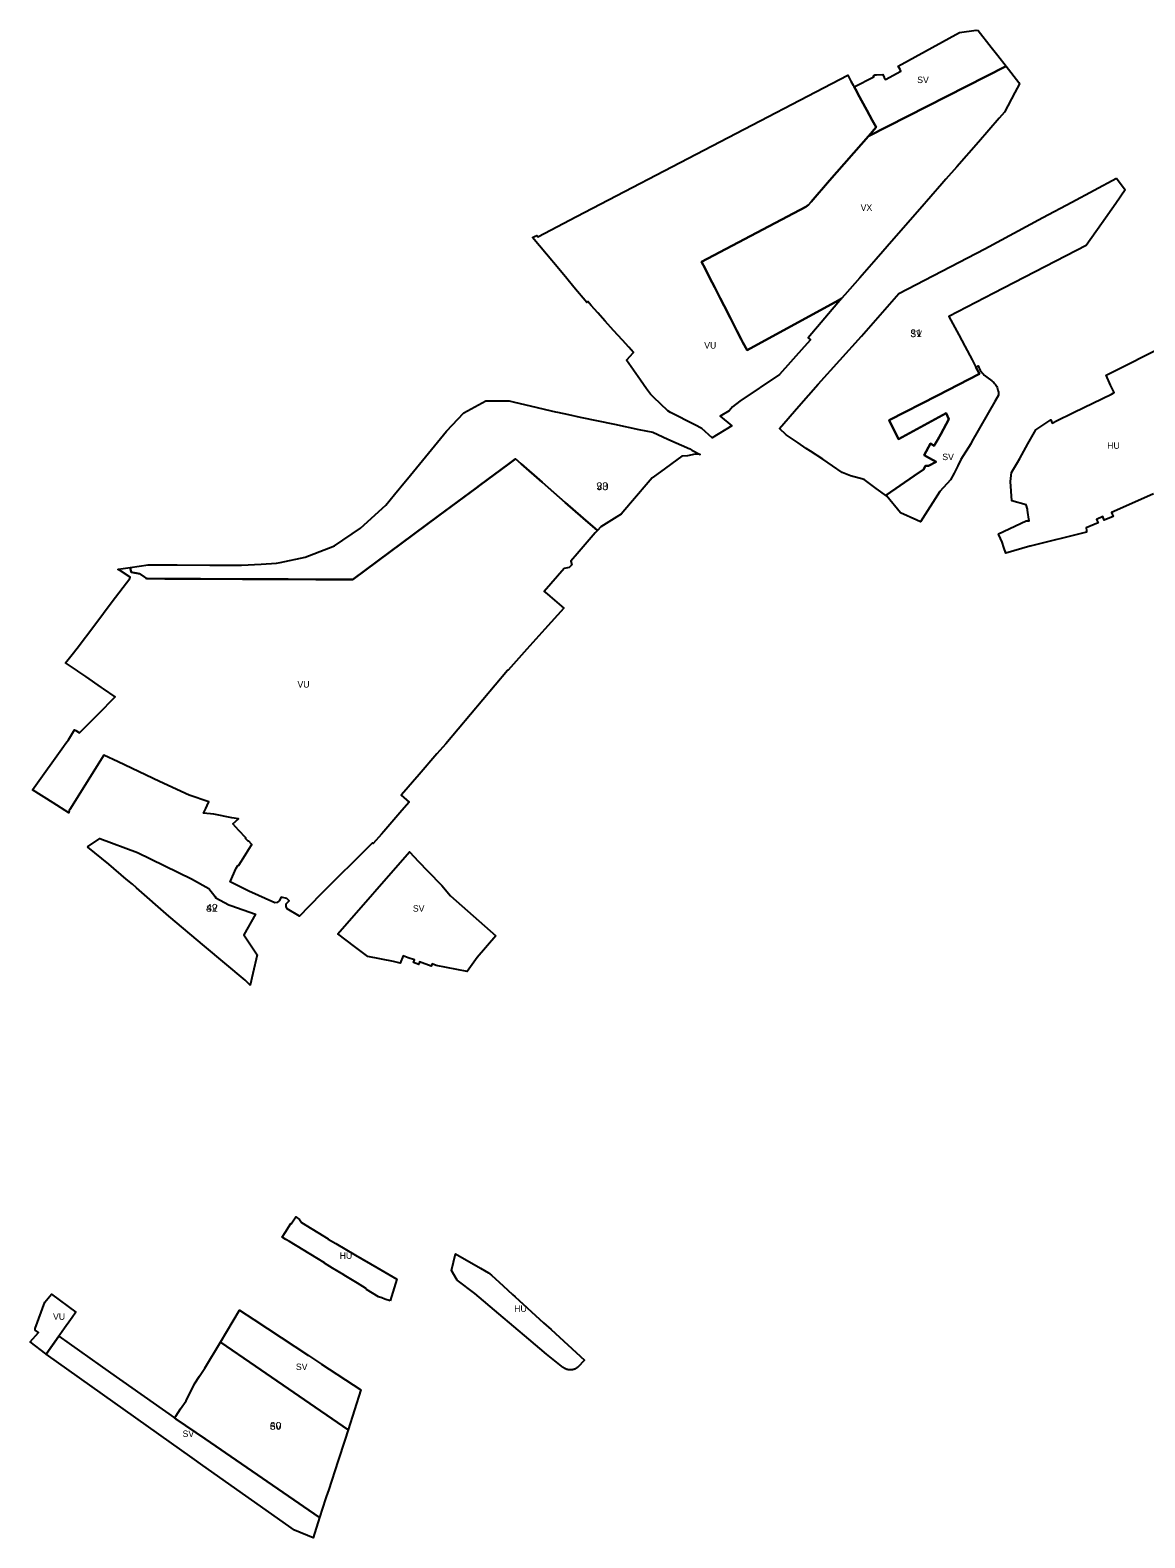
# Model space of a CAD drawing. Extents: x -537011 to -534997, y -1176103 to -1174159.
# Drawn here: x -536797 to -535938, y -1176103 to -1174942 of the extents above; entities that cross this region are included whole.
import ezdxf

# ---------------------------------------------------------------- set-up
doc = ezdxf.new("R2010")
doc.units = 0
for name, color, linetype in [('90510013', 7, 'Continuous'), ('90510023', 7, 'Continuous'), ('90530013', 7, 'Continuous'), ('90570013', 7, 'Continuous'), ('90570023', 7, 'Continuous'), ('90610013', 7, 'Continuous'), ('ID_navrh', 7, 'Continuous')]:
    doc.layers.add(name, color=color, linetype=linetype)

msp = doc.modelspace()

# ---------------------------------------------------------------- linework, layer by layer
at = {"layer": '90510013'}
for points in [[(-536045.18, -1174970.17), (-536045.73, -1174970.45), (-536151.28, -1175023.87), (-536145.37, -1175017.08), (-536148.37, -1175011.57), (-536152.47, -1175004.02), (-536159.31, -1174991.43), (-536160.25, -1174989.71), (-536162.24, -1174986.05), (-536147, -1174978.2), (-536147.32, -1174977.4), (-536146.01, -1174976.8), (-536145.01, -1174976.76), (-536140.21, -1174976.54), (-536138.99, -1174978.78), (-536138.15, -1174980.33), (-536126.13, -1174973.87), (-536126.86, -1174972.63), (-536128.29, -1174970.2), (-536081.08, -1174944.24), (-536068.21, -1174942.34), (-536066.78, -1174942.48), (-536056.76, -1174955.33), (-536051.59, -1174961.96)], [(-536136.94, -1175301.28), (-536137.54, -1175300.54), (-536115.98, -1175285.62), (-536108.91, -1175280.72), (-536107.34, -1175278), (-536104.81, -1175277.91), (-536098.94, -1175274.82), (-536104.15, -1175271.89), (-536108.34, -1175269.54), (-536103.41, -1175260.78), (-536100.55, -1175262.46), (-536100.03, -1175261.54), (-536097.74, -1175257.55), (-536095.46, -1175253.58), (-536089.15, -1175241.96), (-536091.37, -1175237.36), (-536128.04, -1175257.3), (-536135.13, -1175242.6), (-536098, -1175223.64), (-536065.59, -1175207.09), (-536068.42, -1175201.8), (-536066.77, -1175200.96), (-536066.26, -1175202.08), (-536065.69, -1175203.16), (-536065.05, -1175204.21), (-536064.36, -1175205.22), (-536063.6, -1175206.19), (-536062.79, -1175207.11), (-536061.93, -1175207.99), (-536061.02, -1175208.81), (-536060.06, -1175209.57), (-536056.07, -1175212.52), (-536055.33, -1175213.1), (-536054.64, -1175213.73), (-536053.99, -1175214.42), (-536053.41, -1175215.15), (-536052.88, -1175215.93), (-536052.42, -1175216.75), (-536052.02, -1175217.6), (-536051.69, -1175218.48), (-536051.43, -1175219.38), (-536051.24, -1175220.3), (-536051.12, -1175221.23), (-536051.08, -1175222.17), (-536051.13, -1175223.39), (-536053.84, -1175228.22), (-536058.69, -1175236.86), (-536066.56, -1175250.59), (-536071.45, -1175259.11), (-536072.44, -1175260.84), (-536079.94, -1175273.05), (-536082.34, -1175277.81), (-536085.27, -1175283.61), (-536088.03, -1175288.6), (-536096.32, -1175297.69), (-536111.06, -1175320.99), (-536113.86, -1175319.75), (-536126.39, -1175314.2)], [(-536438.2, -1175639.85), (-536452.58, -1175656.54), (-536460.22, -1175667.35), (-536468.28, -1175665.81), (-536484.22, -1175662.75), (-536484.19, -1175662.58), (-536487.36, -1175661.38), (-536488.15, -1175663.14), (-536496.94, -1175659.94), (-536497.69, -1175661.96), (-536501.75, -1175660.46), (-536501.02, -1175658.45), (-536505.74, -1175656.72), (-536509.74, -1175655.18), (-536511.84, -1175660.79), (-536517.13, -1175659.73), (-536536.94, -1175655.74), (-536547.03, -1175648.06), (-536553.54, -1175643.15), (-536560.04, -1175638.23), (-536504.76, -1175575.16), (-536497.76, -1175582.55), (-536490.76, -1175589.93), (-536479.81, -1175600.97), (-536473.11, -1175608.92)], [(-536552.03, -1176020.35), (-536623.36, -1175971.27), (-536650.39, -1175952.67), (-536635.62, -1175928.21), (-536624.7, -1175935.39), (-536582.47, -1175963.15), (-536572.61, -1175969.63), (-536542.24, -1175989.59)], [(-536774.84, -1175948.16), (-536735.05, -1175976.3), (-536685.79, -1176011.14), (-536684.52, -1176012.04), (-536662.25, -1176027.33), (-536574.14, -1176087.83), (-536579.09, -1176103.49), (-536593.43, -1176097.56), (-536663.87, -1176047.79), (-536672.22, -1176041.85), (-536784.64, -1175961.96)]]:
    msp.add_lwpolyline(points, close=True, dxfattribs=at)
at = {"layer": '90510023'}
for points in [[(-535960.11, -1175056.29), (-535953.43, -1175065.31), (-535960.73, -1175075.89), (-535971.74, -1175091.4), (-535983.6, -1175108.09), (-536054.62, -1175144.91), (-536089.24, -1175162.86), (-536081.63, -1175177.09), (-536077.03, -1175185.69), (-536071.39, -1175196.25), (-536068.42, -1175201.8), (-536065.59, -1175207.09), (-536098, -1175223.64), (-536135.13, -1175242.6), (-536128.04, -1175257.3), (-536091.37, -1175237.36), (-536089.15, -1175241.96), (-536095.46, -1175253.58), (-536097.74, -1175257.55), (-536100.03, -1175261.54), (-536100.55, -1175262.46), (-536103.41, -1175260.78), (-536108.34, -1175269.54), (-536104.15, -1175271.89), (-536098.94, -1175274.82), (-536104.81, -1175277.91), (-536107.34, -1175278), (-536108.91, -1175280.72), (-536115.98, -1175285.62), (-536137.54, -1175300.54), (-536136.94, -1175301.28), (-536145.13, -1175295.25), (-536154.59, -1175288.29), (-536165.09, -1175285.55), (-536171.39, -1175283.12), (-536186.22, -1175272.68), (-536195.9, -1175266.57), (-536199.13, -1175264.55), (-536205.32, -1175260.27), (-536214.58, -1175253.88), (-536219.68, -1175249.12), (-536204.88, -1175232.04), (-536189.92, -1175215.07), (-536156.5, -1175178.11), (-536127.83, -1175145.22), (-536061.58, -1175110.73), (-536016.75, -1175086.68), (-535994.48, -1175074.73)], [(-536752.82, -1175571.39), (-536743.31, -1175564.8), (-536714.23, -1175575.68), (-536672.73, -1175595.94), (-536659.38, -1175603.38), (-536654.82, -1175609.37), (-536653.91, -1175610.57), (-536643.86, -1175615.91), (-536642.39, -1175616.44), (-536623.43, -1175623.26), (-536632.47, -1175639.06), (-536622.16, -1175654.48), (-536625.43, -1175668.78), (-536627.48, -1175677.77), (-536631.47, -1175674.03), (-536662.6, -1175647.71), (-536690.07, -1175624.63), (-536715.2, -1175602.87), (-536718.06, -1175600.17), (-536722.97, -1175596.13), (-536736.49, -1175584.54), (-536752.68, -1175571.49)], [(-536552.03, -1176020.35), (-536554.59, -1176028.19), (-536559.74, -1176043.94), (-536562.3, -1176051.77), (-536564.71, -1176059.12), (-536567.28, -1176066.97), (-536567.75, -1176068.42), (-536569.12, -1176072.57), (-536569.43, -1176073.52), (-536571.73, -1176080.52), (-536574.14, -1176087.83), (-536662.25, -1176027.33), (-536684.52, -1176012.04), (-536685.79, -1176011.14), (-536684.83, -1176009.74), (-536681.15, -1176004.24), (-536676.93, -1175997.93), (-536670.42, -1175984.79), (-536666.54, -1175978.89), (-536662.55, -1175972.82), (-536650.39, -1175952.67), (-536623.36, -1175971.27)]]:
    msp.add_lwpolyline(points, close=True, dxfattribs=at)
at = {"layer": '90530013'}
msp.add_lwpolyline([(-535931.61, -1175299.47), (-535962.27, -1175313.07), (-535963.93, -1175313.84), (-535962.64, -1175316.84), (-535969.56, -1175319.81), (-535970.74, -1175317.01), (-535975.41, -1175319.17), (-535974.27, -1175321.85), (-535983.37, -1175325.73), (-535983.27, -1175327.65), (-535983.2, -1175328.86), (-536026.63, -1175339.73), (-536026.8, -1175339.78), (-536045.32, -1175345.23), (-536046.78, -1175340.8), (-536048.17, -1175336.56), (-536050.74, -1175331.13), (-536051.03, -1175330.31), (-536029.77, -1175320.33), (-536027.44, -1175320.35), (-536027.63, -1175319.02), (-536028.39, -1175313.76), (-536028.63, -1175312.06), (-536028.73, -1175311.35), (-536029.59, -1175307.87), (-536040.85, -1175304.92), (-536041.7, -1175289.93), (-536040.89, -1175283.14), (-536036.5, -1175275.39), (-536034.68, -1175272.17), (-536028.36, -1175261.04), (-536022.18, -1175250.17), (-536010.73, -1175242.37), (-536009.65, -1175244.97), (-536005.74, -1175243.07), (-535994.16, -1175237.43), (-535992.6, -1175236.67), (-535963.9, -1175222.62), (-535961.82, -1175221.41), (-535964.85, -1175215.84), (-535968.03, -1175207.99), (-535920.43, -1175184.26)], dxfattribs=at)
for points in [[(-536519.66, -1175920.91), (-536523.68, -1175919.59), (-536526.21, -1175918.76), (-536528.76, -1175917.93), (-536537.78, -1175912.21), (-536538.75, -1175911.1), (-536544.75, -1175907.46), (-536555.16, -1175901.17), (-536555.39, -1175901.03), (-536563.99, -1175895.74), (-536570.3, -1175891.85), (-536570.37, -1175891.81), (-536576.19, -1175888.22), (-536597.11, -1175875.34), (-536599.93, -1175873.6), (-536602.75, -1175871.86), (-536600.49, -1175868.42), (-536596.1, -1175861.52), (-536595.9, -1175861.65), (-536592.45, -1175856.35), (-536589.46, -1175858.3), (-536587.91, -1175860.5), (-536567.36, -1175873.29), (-536567.41, -1175873.4), (-536561.53, -1175876.87), (-536546.41, -1175885.87), (-536529.9, -1175895.34), (-536514.46, -1175904.33)], [(-536467.96, -1175905.16), (-536472.39, -1175897.49), (-536470.92, -1175891.24), (-536469.41, -1175884.86), (-536450.19, -1175895.76), (-536443.86, -1175899.47), (-536441.67, -1175901.22), (-536432.71, -1175909.34), (-536425.32, -1175916.08), (-536423.35, -1175917.87), (-536401.48, -1175937.81), (-536395.7, -1175943.08), (-536369.83, -1175966.66), (-536375.05, -1175971.98), (-536375.36, -1175972.29), (-536375.81, -1175972.62), (-536376.15, -1175972.84), (-536376.33, -1175972.94), (-536376.64, -1175973.12), (-536376.93, -1175973.26), (-536377.19, -1175973.38), (-536377.43, -1175973.48), (-536377.65, -1175973.57), (-536378.05, -1175973.71), (-536378.66, -1175973.89), (-536379.1, -1175973.98), (-536379.46, -1175974.05), (-536379.72, -1175974.08), (-536380.08, -1175974.11), (-536380.55, -1175974.14), (-536381.02, -1175974.15), (-536381.55, -1175974.12), (-536382.01, -1175974.07), (-536382.51, -1175973.99), (-536383.02, -1175973.87), (-536383.46, -1175973.75), (-536383.86, -1175973.62), (-536384.14, -1175973.53), (-536384.39, -1175973.41), (-536384.79, -1175973.23), (-536385.17, -1175973.03), (-536385.56, -1175972.81), (-536385.87, -1175972.61), (-536386.19, -1175972.38), (-536386.43, -1175972.19), (-536399.2, -1175961.97), (-536412.76, -1175950.53), (-536436.07, -1175930.86), (-536454.41, -1175915.38)]]:
    msp.add_lwpolyline(points, close=True, dxfattribs=at)
at = {"layer": '90570013'}
for points in [[(-536271.65, -1175031.44), (-536167.15, -1174977.02), (-536164.96, -1174981.04), (-536164.66, -1174981.59), (-536163.02, -1174984.62), (-536162.42, -1174985.71), (-536162.24, -1174986.05), (-536160.25, -1174989.71), (-536159.31, -1174991.43), (-536152.47, -1175004.02), (-536148.37, -1175011.57), (-536145.37, -1175017.08), (-536151.28, -1175023.87), (-536181.15, -1175058.17), (-536195.41, -1175074.54), (-536197.48, -1175076.92), (-536199.54, -1175078.53), (-536279.71, -1175120.65), (-536277, -1175125.95), (-536273.53, -1175132.76), (-536269.53, -1175140.6), (-536265.39, -1175148.71), (-536262.3, -1175154.77), (-536257.52, -1175164.12), (-536252.55, -1175173.87), (-536249.28, -1175180.28), (-536247.95, -1175182.88), (-536244.7, -1175188.78), (-536174.55, -1175150.52), (-536171.85, -1175149.13), (-536197.75, -1175179.34), (-536195.87, -1175180.85), (-536200.72, -1175186.28), (-536219.8, -1175207.64), (-536250.18, -1175228.11), (-536255.83, -1175232.42), (-536258.52, -1175235.47), (-536265.43, -1175239.57), (-536256.34, -1175246.96), (-536271.48, -1175256.23), (-536279.45, -1175249.03), (-536284.85, -1175246.29), (-536303.62, -1175236.76), (-536305.84, -1175235.63), (-536316.81, -1175225.04), (-536319.19, -1175222.74), (-536322.16, -1175218.49), (-536326.78, -1175211.87), (-536332.16, -1175204.17), (-536337.47, -1175196.56), (-536337.02, -1175196.03), (-536332.81, -1175191.09), (-536332.33, -1175190.53), (-536335.92, -1175186.53), (-536340.72, -1175181.18), (-536347.53, -1175173.58), (-536353.92, -1175166.46), (-536359.75, -1175159.95), (-536364.74, -1175154.39), (-536367.46, -1175151.36), (-536368.14, -1175152.02), (-536378.06, -1175140.2), (-536383.62, -1175133.58), (-536389.8, -1175126.23), (-536399.34, -1175114.87), (-536410.03, -1175102.14), (-536407.88, -1175101.01), (-536406.67, -1175100.37), (-536406.02, -1175101.41), (-536376.08, -1175085.82)], [(-536720.06, -1175356.19), (-536719.23, -1175359.82), (-536712.51, -1175360.94), (-536708.72, -1175363.66), (-536707.87, -1175364.27), (-536707.17, -1175364.77), (-536693.38, -1175364.83), (-536670.44, -1175364.93), (-536665.88, -1175364.95), (-536633.53, -1175365.09), (-536630.46, -1175365.1), (-536617.68, -1175365.16), (-536598.12, -1175365.24), (-536576.99, -1175365.33), (-536565.59, -1175365.38), (-536554.84, -1175365.43), (-536548.53, -1175365.46), (-536482.38, -1175316.47), (-536453.13, -1175294.81), (-536450.77, -1175293.06), (-536428.18, -1175276.34), (-536423.12, -1175272.59), (-536418.82, -1175276.34), (-536402.66, -1175290.43), (-536397.99, -1175294.51), (-536384.79, -1175306.02), (-536370.91, -1175318.13), (-536359.99, -1175327.66), (-536361.65, -1175329.57), (-536375.6, -1175345.56), (-536380.6, -1175351.29), (-536379.74, -1175354.25), (-536381.74, -1175356.21), (-536385.53, -1175356.93), (-536400.91, -1175374.57), (-536398.63, -1175376.55), (-536396.65, -1175378.26), (-536385.98, -1175387.51), (-536400.46, -1175403.61), (-536414.4, -1175419.11), (-536428.82, -1175435.33), (-536429.2, -1175435.56), (-536476.88, -1175491.96), (-536483.59, -1175499.65), (-536497.42, -1175515.55), (-536511.02, -1175531.18), (-536511.29, -1175531.46), (-536504.9, -1175536.8), (-536510.62, -1175543.44), (-536519.88, -1175554.19), (-536521.41, -1175555.97), (-536524.48, -1175559.53), (-536526.41, -1175561.66), (-536532.78, -1175568.71), (-536533.39, -1175568.16), (-536574, -1175608.87), (-536580.31, -1175615.27), (-536582.21, -1175617.2), (-536589.63, -1175624.73), (-536598.9, -1175619.06), (-536599.89, -1175617.24), (-536599.82, -1175615.2), (-536597.56, -1175612.88), (-536599.34, -1175611.14), (-536603.52, -1175610.04), (-536605.3, -1175612.9), (-536606.62, -1175614.07), (-536608.62, -1175614.38), (-536628.44, -1175605.4), (-536639.79, -1175599.9), (-536642.94, -1175598.37), (-536638.25, -1175587.62), (-536637.02, -1175585.59), (-536636.18, -1175585.52), (-536631.43, -1175577.77), (-536628.6, -1175573.16), (-536626.3, -1175569.43), (-536628.82, -1175566.69), (-536629.16, -1175567), (-536631.2, -1175564.78), (-536630.86, -1175564.46), (-536636.19, -1175558.64), (-536640.86, -1175553.55), (-536636.61, -1175549.66), (-536641.71, -1175549.09), (-536655.59, -1175546.25), (-536663.39, -1175545.39), (-536661.77, -1175541.78), (-536660.75, -1175539.52), (-536659.47, -1175536.67), (-536674.62, -1175531.43), (-536697.28, -1175520.87), (-536729.21, -1175505.96), (-536740.27, -1175500.8), (-536766.47, -1175542.55), (-536766.92, -1175543.35), (-536767.24, -1175545.07), (-536779.19, -1175537.47), (-536795.1, -1175527.36), (-536793.88, -1175525.65), (-536771.31, -1175494.15), (-536769.48, -1175491.59), (-536767.57, -1175488.92), (-536762.77, -1175481.28), (-536761.91, -1175481.8), (-536759.05, -1175483.52), (-536757.27, -1175481.73), (-536744.68, -1175469.05), (-536731.46, -1175455.74), (-536740.56, -1175449.53), (-536742.05, -1175448.52), (-536754.2, -1175440.24), (-536760.3, -1175436.09), (-536760.66, -1175435.84), (-536769.67, -1175429.7), (-536765.73, -1175424.53), (-536764.72, -1175423.21), (-536760.9, -1175418.19), (-536747.31, -1175400.34), (-536733.71, -1175382.48), (-536720.19, -1175364.72), (-536720.16, -1175364.6), (-536719.85, -1175363.51), (-536727.42, -1175358.87), (-536729.44, -1175357.63), (-536728.94, -1175357.47)], [(-536774.84, -1175948.16), (-536784.64, -1175961.96), (-536784.85, -1175961.81), (-536797.02, -1175952.45), (-536790.71, -1175945.24), (-536793.05, -1175943.52), (-536793.19, -1175942.19), (-536785.59, -1175921.87), (-536780.5, -1175915.75), (-536761.77, -1175929.76), (-536764.61, -1175933.77), (-536765.93, -1175935.63), (-536770.43, -1175942), (-536774.14, -1175947.25)]]:
    msp.add_lwpolyline(points, close=True, dxfattribs=at)
at = {"layer": '90570023'}
msp.add_lwpolyline([(-536720.06, -1175356.19), (-536706.02, -1175354.17), (-536703.09, -1175354.18), (-536683.84, -1175354.25), (-536658.65, -1175354.34), (-536647.1, -1175354.38), (-536635.72, -1175354.42), (-536634.14, -1175354.33), (-536619.04, -1175353.49), (-536607.28, -1175352.83), (-536604.35, -1175352.21), (-536585.26, -1175348.14), (-536567.18, -1175341.2), (-536562.54, -1175339.42), (-536542.56, -1175325.99), (-536523.05, -1175308.22), (-536516.21, -1175299.87), (-536507.78, -1175289.57), (-536506.39, -1175287.87), (-536476.37, -1175251.23), (-536462.81, -1175237.16), (-536445.98, -1175227.76), (-536444.75, -1175227.76), (-536427.89, -1175227.8), (-536423.97, -1175228.74), (-536407.33, -1175232.74), (-536399.98, -1175234.5), (-536392.21, -1175236.37), (-536390.81, -1175236.66), (-536382.24, -1175238.45), (-536373.21, -1175240.34), (-536346.89, -1175245.84), (-536328.04, -1175249.78), (-536317.26, -1175252.03), (-536305.74, -1175257.27), (-536288.93, -1175264.91), (-536287.16, -1175265.83), (-536280.96, -1175269.04), (-536284.76, -1175268.91), (-536290.53, -1175270.13), (-536294.87, -1175270.55), (-536311.39, -1175282.57), (-536317.76, -1175287.21), (-536334.39, -1175306.56), (-536341.62, -1175314.98), (-536345.13, -1175317.2), (-536357.28, -1175324.87), (-536359.99, -1175327.66), (-536370.91, -1175318.13), (-536384.79, -1175306.02), (-536397.99, -1175294.51), (-536402.66, -1175290.43), (-536418.82, -1175276.34), (-536423.12, -1175272.59), (-536428.18, -1175276.34), (-536450.77, -1175293.06), (-536453.13, -1175294.81), (-536482.38, -1175316.47), (-536548.53, -1175365.46), (-536554.84, -1175365.43), (-536565.59, -1175365.38), (-536576.99, -1175365.33), (-536598.12, -1175365.24), (-536617.68, -1175365.16), (-536630.46, -1175365.1), (-536633.53, -1175365.09), (-536665.88, -1175364.95), (-536670.44, -1175364.93), (-536693.38, -1175364.83), (-536707.17, -1175364.77), (-536707.87, -1175364.27), (-536708.72, -1175363.66), (-536712.51, -1175360.94), (-536719.23, -1175359.82)], close=True, dxfattribs=at)
at = {"layer": '90610013'}
msp.add_lwpolyline([(-536045.18, -1174970.17), (-536035.38, -1174982.75), (-536034.72, -1174983.59), (-536038.38, -1174990.43), (-536046.43, -1175005.49), (-536050.45, -1175010.1), (-536066.52, -1175028.5), (-536083.18, -1175047.59), (-536091.51, -1175057.14), (-536094.69, -1175060.78), (-536111.69, -1175080.24), (-536131.68, -1175103.11), (-536145.36, -1175118.77), (-536157.93, -1175133.14), (-536169.31, -1175146.17), (-536171.85, -1175149.13), (-536174.55, -1175150.52), (-536244.7, -1175188.78), (-536247.95, -1175182.88), (-536249.28, -1175180.28), (-536252.55, -1175173.87), (-536257.52, -1175164.12), (-536262.3, -1175154.77), (-536265.39, -1175148.71), (-536269.53, -1175140.6), (-536273.53, -1175132.76), (-536277, -1175125.95), (-536279.71, -1175120.65), (-536199.54, -1175078.53), (-536197.48, -1175076.92), (-536195.41, -1175074.54), (-536181.15, -1175058.17), (-536151.28, -1175023.87), (-536045.73, -1174970.45)], close=True, dxfattribs=at)

# ---------------------------------------------------------------- texts
at = {"layer": '90510013'}
for rotation, p in [(360, (-536113.628, -1174983.105)), (0, (-536094.31, -1175273.474)), (0, (-536502.175, -1175621.255)), (0, (-536592.26, -1175974.28)), (360, (-536679.606, -1176025.825))]:
    msp.add_text('SV', height=5, rotation=rotation, dxfattribs=at).set_placement(p)
at = {"layer": '90510023'}
for rotation, p in [(360, (-536118.917, -1175178.785)), (0, (-536661.427, -1175621.285)), (0, (-536612.369, -1176020.25))]:
    msp.add_text('SV', height=5, rotation=rotation, dxfattribs=at).set_placement(p)
at = {"layer": '90530013'}
for rotation, p in [(360, (-535967.28, -1175264.745)), (0, (-536558.562, -1175888.63)), (360, (-536424.132, -1175929.505))]:
    msp.add_text('HU', height=5, rotation=rotation, dxfattribs=at).set_placement(p)
at = {"layer": '90570013'}
msp.add_text('VU', height=5, dxfattribs=at).set_placement((-536277.7, -1175187.596))
for rotation, p in [(0, (-536591.059, -1175448.66)), (360, (-536779.395, -1175935.575))]:
    msp.add_text('VU', height=5, rotation=rotation, dxfattribs=at).set_placement(p)
at = {"layer": '90570023'}
msp.add_text('VU', height=5, rotation=0, dxfattribs=at).set_placement((-536360.71, -1175296.61))
at = {"layer": '90610013'}
msp.add_text('VX', height=5, rotation=360, dxfattribs=at).set_placement((-536157.215, -1175081.504))
at = {"layer": 'ID_navrh'}
for s, rotation, p in [('31', 360, (-536118.917, -1175178.785)), ('33', 0, (-536360.71, -1175296.61)), ('42', 0, (-536661.427, -1175621.285)), ('60', 0, (-536612.369, -1176020.25))]:
    msp.add_text(s, height=6, rotation=rotation, dxfattribs=at).set_placement(p)

doc.saveas('drawing.dxf')
